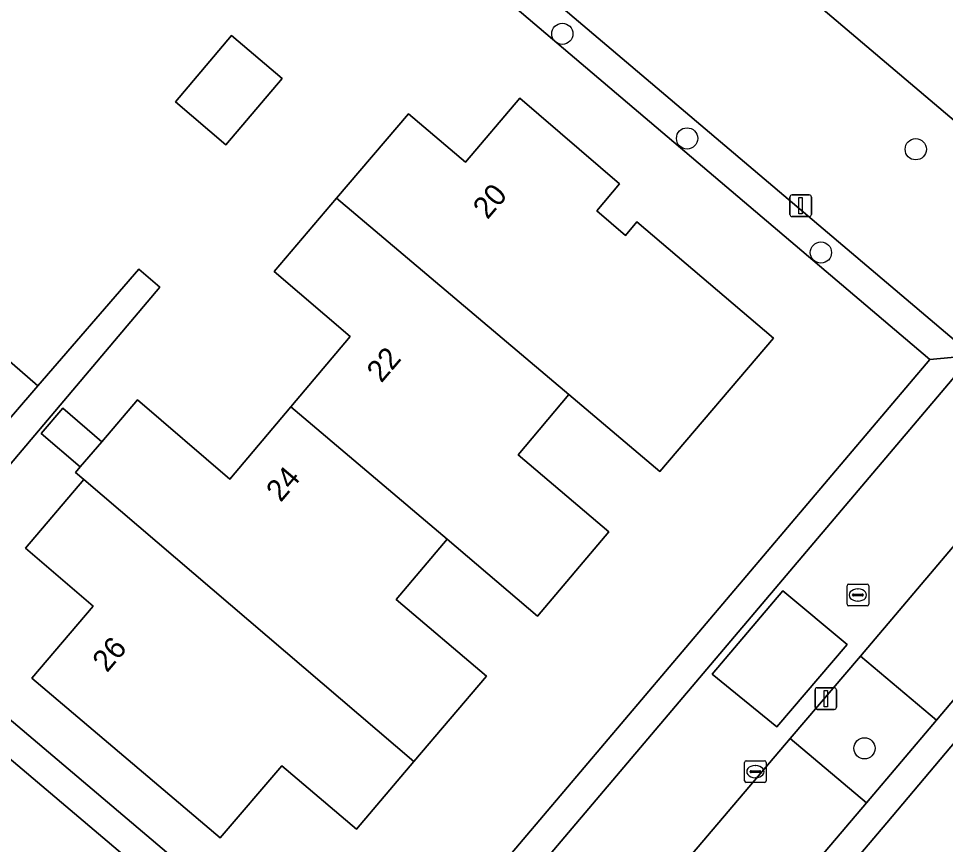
# Model space of a CAD drawing. Extents: x 156412 to 157779, y 382335 to 383768.
# Drawn here: x 156882.21 to 156924.94, y 382391.25 to 382429.31 of the extents above; entities that cross this region are included whole.
import ezdxf

# ---------------------------------------------------------------- set-up
doc = ezdxf.new("R2010")
doc.units = 0
for name, color, linetype in [('IMGEO_Berm_groen', 7, 'Continuous'), ('IMGEO_Boom', 7, 'Continuous'), ('IMGEO_Erf', 7, 'Continuous'), ('IMGEO_Groenvoorziening', 7, 'Continuous'), ('IMGEO_Kolk', 7, 'Continuous'), ('IMGEO_Lichtmast', 7, 'Continuous'), ('IMGEO_Pand', 7, 'Continuous'), ('IMGEO_Pand_nummerreeks', 7, 'Continuous'), ('IMGEO_Parkeervlak_open', 7, 'Continuous'), ('IMGEO_Rijbaan_lokaal_open', 7, 'Continuous'), ('IMGEO_Rioolput', 7, 'Continuous'), ('IMGEO_Voetpad_open', 7, 'Continuous')]:
    doc.layers.add(name, color=color, linetype=linetype)

msp = doc.modelspace()

# ---------------------------------------------------------------- linework, layer by layer
at = {"layer": 'IMGEO_Berm_groen'}
for points in [[(156926.24, 382423.851), (156886.177, 382457.81)], [(156881.842, 382451.382), (156926.041, 382413.904), (156926.625, 382414.568), (156927.038, 382415.052)]]:
    msp.add_lwpolyline(points, dxfattribs=at)
msp.add_lwpolyline([(156924.524, 382396.985), (156921.019, 382399.928), (156917.784, 382396.135), (156921.291, 382393.174)], close=True, dxfattribs=at)
at = {"layer": 'IMGEO_Boom'}
for centre in [(156907.275, 382428.61), (156913.028, 382423.789), (156923.569, 382423.29), (156919.197, 382418.53), (156921.206, 382395.682)]:
    msp.add_circle(centre, 0.489, dxfattribs=at)
at = {"layer": 'IMGEO_Erf'}
for points in [[(156924.214, 382413.601), (156903.563, 382431.149), (156881.734, 382449.671), (156857.229, 382420.763)], [(156857.185, 382417.834), (156874.942, 382402.819), (156879.807, 382408.572), (156877.423, 382410.629), (156880.711, 382414.439), (156883.099, 382412.382), (156887.749, 382417.764), (156888.719, 382416.926), (156876.01, 382401.916), (156893.156, 382387.398)], [(156902.659, 382388.166), (156924.214, 382413.601)]]:
    msp.add_lwpolyline(points, dxfattribs=at)
for points in [[(156891.77, 382423.499), (156889.443, 382425.474), (156892.03, 382428.529), (156894.357, 382426.545)], [(156899.61, 382402.546), (156903.783, 382399), (156900.433, 382395.069), (156897.786, 382391.962), (156894.341, 382394.876), (156891.509, 382391.556), (156882.823, 382398.912), (156885.641, 382402.237), (156882.527, 382404.898), (156885.22, 382408.07), (156884.837, 382408.398), (156885.049, 382408.646), (156883.249, 382410.189), (156884.243, 382411.35), (156886.044, 382409.807), (156887.696, 382411.735), (156891.955, 382408.087), (156894.766, 382411.419), (156897.501, 382414.661), (156893.997, 382417.658), (156896.871, 382421.032), (156900.186, 382424.924), (156902.814, 382422.688), (156905.315, 382425.639), (156909.905, 382421.696), (156908.867, 382420.449), (156910.192, 382419.316), (156910.709, 382419.938), (156917.007, 382414.589), (156911.77, 382408.443), (156907.579, 382411.984), (156905.236, 382409.206), (156909.42, 382405.657), (156906.137, 382401.77), (156901.962, 382405.313)]]:
    msp.add_lwpolyline(points, close=True, dxfattribs=at)
at = {"layer": 'IMGEO_Groenvoorziening'}
msp.add_lwpolyline([(157007.195, 382502.44), (157001.79, 382496.06), (156999.613, 382493.491), (156945.456, 382429.481), (156942.049, 382425.461), (156946.916, 382421.548), (156922.237, 382392.249), (156899.797, 382365.794), (156900.614, 382364.989), (156880.618, 382342.431), (156887.078, 382336.95), (156893.199, 382344.307), (157056.005, 382537.641)], dxfattribs=at)
at = {"layer": 'IMGEO_Kolk'}
for p, q in [((156915.676, 382394.181), (156915.676, 382395.033)), ((156915.751, 382395.107), (156916.603, 382395.107)), ((156916.677, 382395.033), (156916.677, 382394.181)), ((156915.935, 382394.601), (156915.935, 382394.613)), ((156916.373, 382394.564), (156915.975, 382394.564)), ((156915.978, 382394.65), (156916.376, 382394.65)), ((156916.164, 382394.887), (156916.189, 382394.887)), ((156916.419, 382394.613), (156916.419, 382394.601)), ((156916.603, 382394.107), (156915.751, 382394.107)), ((156916.187, 382394.327), (156916.162, 382394.327))]:
    msp.add_line(p, q, dxfattribs=at)
for points in [[(156915.676, 382394.181), (156915.676, 382395.033)], [(156915.751, 382395.107), (156916.603, 382395.107)], [(156916.677, 382395.033), (156916.677, 382394.181)], [(156916.603, 382394.107), (156915.751, 382394.107)]]:
    msp.add_lwpolyline(points, dxfattribs=at)
for centre, radius, start, end in [((156915.753, 382395.031), 0.0765, 91.552, 178.448), ((156915.753, 382395.031), 0.0765, 91.552, 178.448), ((156916.601, 382395.031), 0.0765, 1.552, 88.448), ((156916.601, 382395.031), 0.0765, 1.552, 88.448), ((156915.975, 382394.61), 0.0403, 85.8775, 175.7526), ((156915.972, 382394.6), 0.0366, 178.938, 274.7102), ((156916.376, 382394.607), 0.043, 264.8664, 352.4533), ((156916.38, 382394.612), 0.0386, 1.7309, 96.639), ((156915.753, 382394.183), 0.0765, 181.552, 268.448), ((156915.753, 382394.183), 0.0765, 181.552, 268.448), ((156916.601, 382394.183), 0.0765, 271.552, 358.448), ((156916.601, 382394.183), 0.0765, 271.552, 358.448)]:
    msp.add_arc(centre, radius, start, end, dxfattribs=at)
for centre, major_axis, ratio, start_param, end_param in [((156916.163, 382394.607), (-0.387, 0.002), 0.722429, 4.712389, 7.853982), ((156916.188, 382394.607), (-0.39, 0.002), 0.717154, 1.570796, 4.712389)]:
    msp.add_ellipse(centre, major_axis=major_axis, ratio=ratio, start_param=start_param, end_param=end_param, dxfattribs=at)
at = {"layer": 'IMGEO_Lichtmast'}
for p, q in [((156917.766, 382420.285), (156917.766, 382421.085)), ((156917.766, 382421.085), (156917.766, 382420.285)), ((156917.866, 382421.185), (156918.656, 382421.185)), ((156918.656, 382421.185), (156917.866, 382421.185)), ((156918.756, 382421.085), (156918.756, 382420.285)), ((156918.756, 382420.285), (156918.756, 382421.085)), ((156918.656, 382420.185), (156917.866, 382420.185)), ((156917.866, 382420.185), (156918.656, 382420.185)), ((156918.925, 382397.571), (156918.925, 382398.371)), ((156918.925, 382398.371), (156918.925, 382397.571)), ((156919.025, 382398.471), (156919.815, 382398.471)), ((156919.815, 382398.471), (156919.025, 382398.471)), ((156919.915, 382398.371), (156919.915, 382397.571)), ((156919.915, 382397.571), (156919.915, 382398.371)), ((156919.815, 382397.471), (156919.025, 382397.471)), ((156919.025, 382397.471), (156919.815, 382397.471))]:
    msp.add_line(p, q, dxfattribs=at)
for points in [[(156918.186, 382421.06), (156918.336, 382421.06), (156918.336, 382420.31), (156918.186, 382420.31), (156918.186, 382421.06)], [(156919.345, 382398.346), (156919.495, 382398.346), (156919.495, 382397.596), (156919.345, 382397.596), (156919.345, 382398.346)]]:
    msp.add_lwpolyline(points, dxfattribs=at)
for centre, start, end in [((156917.866, 382421.085), 90, 180), ((156917.866, 382421.085), 90, 180), ((156918.656, 382421.085), 0, 90), ((156918.656, 382421.085), 360, 90), ((156917.866, 382420.285), 180, 270), ((156917.866, 382420.285), 180, 270), ((156918.656, 382420.285), 270, 0), ((156918.656, 382420.285), 270, 0), ((156919.025, 382398.371), 90, 180), ((156919.025, 382398.371), 90, 180), ((156919.815, 382398.371), 0, 90), ((156919.815, 382398.371), 360, 90), ((156919.025, 382397.571), 180, 270), ((156919.025, 382397.571), 180, 270), ((156919.815, 382397.571), 270, 0), ((156919.815, 382397.571), 270, 0)]:
    msp.add_arc(centre, 0.1, start, end, dxfattribs=at)
at = {"layer": 'IMGEO_Pand'}
for points in [[(156894.357, 382426.545), (156892.03, 382428.529), (156889.443, 382425.474), (156891.77, 382423.499)], [(156900.186, 382424.924), (156896.871, 382421.032), (156907.579, 382411.984), (156911.77, 382408.443), (156917.007, 382414.589), (156910.709, 382419.938), (156910.192, 382419.316), (156908.867, 382420.449), (156909.905, 382421.696), (156905.315, 382425.639), (156902.814, 382422.688)], [(156907.579, 382411.984), (156896.871, 382421.032), (156893.997, 382417.658), (156897.501, 382414.661), (156894.766, 382411.419), (156901.962, 382405.313), (156906.137, 382401.77), (156909.42, 382405.657), (156905.236, 382409.206)], [(156883.099, 382412.382), (156880.711, 382414.439), (156877.423, 382410.629), (156879.807, 382408.572)], [(156901.962, 382405.313), (156894.766, 382411.419), (156891.955, 382408.087), (156887.696, 382411.735), (156886.044, 382409.807), (156885.049, 382408.646), (156884.837, 382408.398), (156885.22, 382408.07), (156900.433, 382395.069), (156903.783, 382399), (156899.61, 382402.546)], [(156885.049, 382408.646), (156886.044, 382409.807), (156884.243, 382411.35), (156883.249, 382410.189)], [(156885.22, 382408.07), (156882.527, 382404.898), (156885.641, 382402.237), (156882.823, 382398.912), (156891.509, 382391.556), (156894.341, 382394.876), (156897.786, 382391.962), (156900.433, 382395.069)]]:
    msp.add_lwpolyline(points, close=True, dxfattribs=at)
at = {"layer": 'IMGEO_Parkeervlak_open'}
for points in [[(156932.656, 382406.607), (156929.162, 382409.541), (156921.019, 382399.928), (156924.524, 382396.985)], [(156921.291, 382393.174), (156917.784, 382396.135), (156907.997, 382384.606), (156911.513, 382381.644)]]:
    msp.add_lwpolyline(points, close=True, dxfattribs=at)
at = {"layer": 'IMGEO_Rijbaan_lokaal_open'}
for points in [[(156826.003, 382508.837), (156830.605, 382504.95), (156831.533, 382504.167), (156832.153, 382503.644), (156844.108, 382493.469), (156884.65, 382459.104), (156886.177, 382457.81), (156926.24, 382423.851), (156926.323, 382423.798), (156934.962, 382417.1), (156941.002, 382424.226), (156942.049, 382425.461), (156945.456, 382429.481), (156999.613, 382493.491), (157001.79, 382496.06), (157007.195, 382502.44)], [(156892.232, 382386.377), (156874.527, 382401.352), (156856.274, 382416.843)], [(156927.038, 382415.052), (156926.625, 382414.568), (156926.041, 382413.904), (156926.185, 382413.78), (156903.742, 382387.286)], [(156905.751, 382381.96), (156906.687, 382383.063), (156907.997, 382384.606), (156917.784, 382396.135), (156921.019, 382399.928), (156929.162, 382409.541)]]:
    msp.add_lwpolyline(points, dxfattribs=at)
for points in [[(156920.408, 382400.467), (156917.447, 382402.945), (156914.18, 382399.102), (156917.169, 382396.665)], [(156920.408, 382400.467), (156917.169, 382396.665), (156914.18, 382399.102), (156917.447, 382402.945)]]:
    msp.add_lwpolyline(points, close=True, dxfattribs=at)
at = {"layer": 'IMGEO_Rioolput'}
for p, q in [((156920.4, 382402.32), (156920.4, 382403.172)), ((156920.475, 382403.246), (156921.327, 382403.246)), ((156920.888, 382403.026), (156920.913, 382403.026)), ((156921.401, 382403.172), (156921.401, 382402.32)), ((156920.659, 382402.74), (156920.659, 382402.752)), ((156921.097, 382402.703), (156920.699, 382402.703)), ((156920.702, 382402.789), (156921.1, 382402.789)), ((156921.143, 382402.752), (156921.143, 382402.74)), ((156921.327, 382402.246), (156920.475, 382402.246)), ((156920.911, 382402.466), (156920.886, 382402.466))]:
    msp.add_line(p, q, dxfattribs=at)
for points in [[(156920.4, 382402.32), (156920.4, 382403.172)], [(156920.475, 382403.246), (156921.327, 382403.246)], [(156921.401, 382403.172), (156921.401, 382402.32)], [(156921.327, 382402.246), (156920.475, 382402.246)]]:
    msp.add_lwpolyline(points, dxfattribs=at)
for centre, radius, start, end in [((156920.477, 382403.17), 0.0765, 91.552, 178.448), ((156920.477, 382403.17), 0.0765, 91.552, 178.448), ((156921.325, 382403.17), 0.0765, 1.552, 88.448), ((156921.325, 382403.17), 0.0765, 1.552, 88.448), ((156920.699, 382402.749), 0.0403, 85.8775, 175.7526), ((156920.696, 382402.739), 0.0366, 178.938, 274.7102), ((156921.1, 382402.746), 0.043, 264.8664, 352.4533), ((156921.104, 382402.751), 0.0386, 1.7309, 96.639), ((156920.477, 382402.322), 0.0765, 181.552, 268.448), ((156920.477, 382402.322), 0.0765, 181.552, 268.448), ((156921.325, 382402.322), 0.0765, 271.552, 358.448), ((156921.325, 382402.322), 0.0765, 271.552, 358.448)]:
    msp.add_arc(centre, radius, start, end, dxfattribs=at)
for centre, major_axis, ratio, start_param, end_param in [((156920.887, 382402.746), (-0.387, 0.002), 0.722429, 4.712389, 7.853982), ((156920.912, 382402.746), (-0.39, 0.002), 0.717154, 1.570796, 4.712389)]:
    msp.add_ellipse(centre, major_axis=major_axis, ratio=ratio, start_param=start_param, end_param=end_param, dxfattribs=at)
at = {"layer": 'IMGEO_Voetpad_open'}
for points in [[(156794.793, 382458.992), (156802.386, 382467.905), (156803.522, 382469.239), (156808.479, 382475.058), (156810.033, 382476.883), (156811.563, 382478.679), (156814.902, 382482.597), (156818.136, 382486.392), (156824.64, 382494.023), (156826.198, 382495.85), (156827.163, 382496.983), (156832.477, 382503.264), (156832.153, 382503.644), (156831.533, 382504.167), (156810.572, 382479.519), (156791.675, 382457.364), (156821.763, 382431.828), (156849.783, 382408.111), (156876.247, 382385.72), (156880.938, 382381.751), (156899.797, 382365.794), (156922.237, 382392.249)], [(156878.866, 382453.93), (156834.843, 382491.235), (156835.001, 382489.257), (156877.342, 382453.394), (156878.396, 382452.501), (156880.689, 382450.557), (156881.734, 382449.671), (156903.563, 382431.149), (156924.214, 382413.601), (156926.185, 382413.78), (156926.041, 382413.904), (156881.842, 382451.382)], [(156922.237, 382392.249), (156946.916, 382421.548), (156942.049, 382425.461), (156941.002, 382424.226), (156944.906, 382421.224), (156934.311, 382408.541), (156930.458, 382411.786), (156929.612, 382410.788), (156933.456, 382407.552), (156932.656, 382406.607), (156924.524, 382396.985), (156921.291, 382393.174), (156911.513, 382381.644), (156910.22, 382380.117), (156901.006, 382369.261)], [(156893.156, 382387.398), (156876.01, 382401.916), (156874.942, 382402.819), (156857.185, 382417.834)], [(156856.274, 382416.843), (156874.527, 382401.352), (156892.232, 382386.377)], [(156926.185, 382413.78), (156924.214, 382413.601), (156902.659, 382388.166)], [(156903.742, 382387.286), (156926.185, 382413.78)]]:
    msp.add_lwpolyline(points, dxfattribs=at)
msp.add_lwpolyline([(156883.099, 382412.382), (156879.807, 382408.572), (156874.942, 382402.819), (156876.01, 382401.916), (156888.719, 382416.926), (156887.749, 382417.764)], close=True, dxfattribs=at)

# ---------------------------------------------------------------- texts
at = {"layer": 'IMGEO_Pand_nummerreeks'}
for s, rotation, p in [('20', 49.5207, (156903.825, 382420.02)), ('22', 49.6525, (156898.934, 382412.487)), ('24', 49.6525, (156894.294, 382406.986)), ('26', 49.5207, (156886.286, 382399.137))]:
    msp.add_text(s, height=1, rotation=rotation, dxfattribs=at).set_placement(p)

doc.saveas('drawing.dxf')
